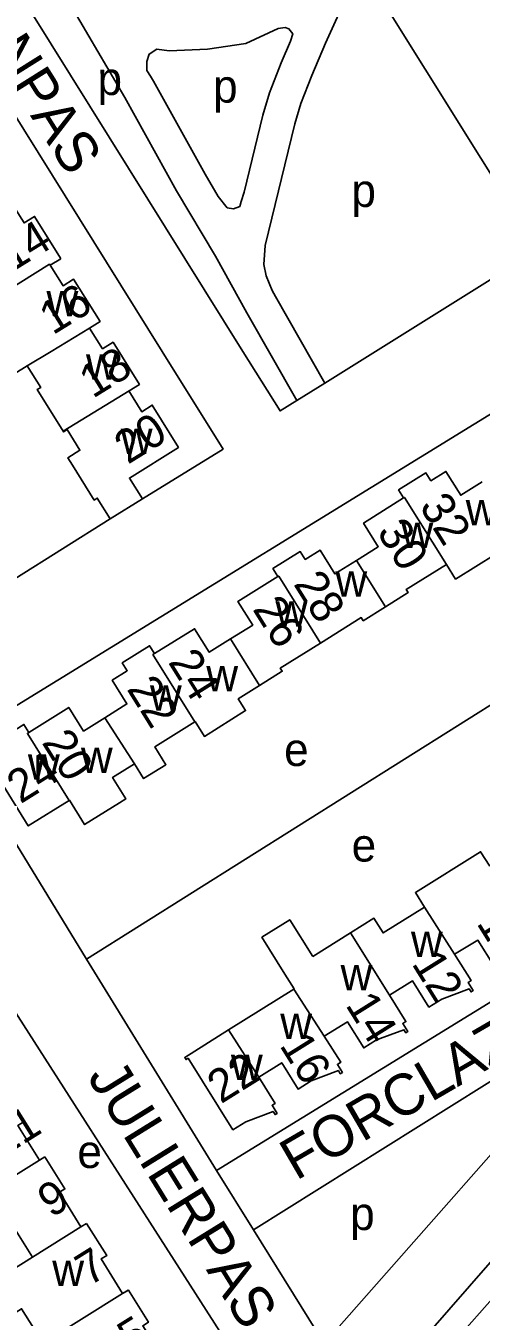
# Model space of a CAD drawing. Extents: x 158848 to 160613, y 385889 to 387762.
# Drawn here: x 159153.5 to 159208.8, y 386865.6 to 387022.2 of the extents above; entities that cross this region are included whole.
import ezdxf

# ---------------------------------------------------------------- set-up
doc = ezdxf.new("R2010")
doc.units = 0
for name, color, linetype in [('BLT_Basislijn', 7, 'Continuous'), ('BLT_Bebouwing', 7, 'Continuous'), ('BLT_Centroide', 7, 'Continuous'), ('BLT_Huisnummer', 7, 'Continuous'), ('BLT_Huisnummer_ tussenligend', 7, 'Continuous'), ('BLT_Onderverdeling_panden', 7, 'Continuous'), ('BLT_Straatnaam', 7, 'Continuous')]:
    doc.layers.add(name, color=color, linetype=linetype)

msp = doc.modelspace()

# ---------------------------------------------------------------- linework, layer by layer
at = {"layer": 'BLT_Basislijn'}
for p, q in [((159127.38, 387051.14), (159170.05, 386982.75)), ((159163.76, 386962.42), (159152.2, 386955.13)), ((159160.9, 386909.02), (159236.2, 386956.34)), ((159160.9, 386909.02), (159176.65, 386883.38)), ((159176.65, 386883.38), (159181.14, 386876.17)), ((159181.14, 386876.17), (159189.75, 386862.37))]:
    msp.add_line(p, q, dxfattribs=at)
for points in [[(159137.97, 387049.83), (159140.6, 387049.83), (159141.98, 387049.49), (159142.97, 387048.99), (159144.37, 387048.23), (159145.02, 387047.58), (159145.74, 387046.72), (159147.69, 387044.46), (159148.49, 387043.39), (159149.49, 387041.67), (159158.97, 387024.7), (159165.54, 387013.55), (159171.8, 387002.23), (159176.54, 386994.29), (159180.35, 386987.43), (159186.41, 386976.78)], [(159179.86, 386982.75), (159137.97, 387049.83)], [(159195.05, 387028.15), (159192.99, 387026.26), (159191.51, 387023.71), (159189.88, 387020.15), (159188.22, 387016.23), (159186.89, 387012.82), (159186.16, 387010.36), (159182.58, 386995.58)], [(159195.05, 387028.15), (159215.7, 386995.08), (159195.96, 386982.75)], [(159170.92, 387019.2), (159175.56, 387019.43), (159180.23, 387020.09), (159184.13, 387021.92)], [(159184.13, 387021.92), (159184.99, 387022.03), (159185.45, 387021.88), (159185.91, 387021.27), (159185.64, 387020.4)], [(159185.64, 387020.4), (159184.52, 387017.74), (159183.1, 387014.12), (159182.3, 387011.39), (159180.04, 387002.06)], [(159170.92, 387019.2), (159169.41, 387019.43), (159168.49, 387018.82), (159168.19, 387017.9), (159168.19, 387016.83), (159168.65, 387016.14)], [(159168.65, 387016.14), (159169.01, 387015.53), (159175.27, 387004.23), (159176.87, 387001.54)], [(159176.87, 387001.54), (159177.97, 387000.17), (159178.73, 387000.02), (159179.49, 387000.33), (159179.65, 387000.94), (159180.04, 387002.06)], [(159182.58, 386995.58), (159182.4, 386993.3), (159182.7, 386991.92), (159183.41, 386990.14)], [(159183.41, 386990.14), (159183.83, 386989.39), (159189.8, 386978.9)], [(159170.05, 386982.75), (159177.46, 386970.89), (159167.66, 386964.86)], [(159186.41, 386976.78), (159184.38, 386975.52), (159179.86, 386982.75)], [(159195.96, 386982.75), (159189.8, 386978.9)], [(159220.45, 386981.6), (159144.84, 386935.16), (159160.9, 386909.02)], [(159189.8, 386978.9), (159186.41, 386976.78)], [(159176.65, 386883.38), (159252.82, 386930.16), (159236.2, 386956.34)], [(159187.49, 386847.55), (159135.54, 386928.59), (159130.53, 386925.54)], [(159194.56, 386854.66), (159251.14, 386919.42), (159256.83, 386923.09), (159267.95, 386905.52), (159267.38, 386904.72)], [(159181.14, 386876.17), (159221.23, 386901.24), (159222.71, 386899.76), (159189.75, 386862.37)]]:
    msp.add_lwpolyline(points, dxfattribs=at)
at = {"layer": 'BLT_Bebouwing'}
for p, q in [((159156.48, 386993.21), (159157.76, 386993.99)), ((159157.76, 386993.99), (159157.72, 386994.05)), ((159166.03, 386977.94), (159166.05, 386977.96)), ((159167.66, 386964.86), (159163.76, 386962.42)), ((159204.59, 386956.9), (159204.57, 386956.88)), ((159174.08, 386937.83), (159174.04, 386937.8)), ((159158.78, 386928.26), (159158.82, 386928.28)), ((159188.36, 386909.32), (159192.94, 386912.19)), ((159186.04, 386905.38), (159178.12, 386900.42)), ((159186.09, 386905.42), (159186.04, 386905.38)), ((159155.16, 386884.62), (159155.84, 386885.04)), ((159155.84, 386885.04), (159155.84, 386885.03)), ((159160.21, 386876.53), (159160.89, 386876.95)), ((159160.89, 386876.95), (159160.9, 386876.93)), ((159165.27, 386868.43), (159165.95, 386868.85)), ((159165.95, 386868.85), (159165.96, 386868.83))]:
    msp.add_line(p, q, dxfattribs=at)
for points in [[(159157.72, 386994.05), (159154.57, 386999.12), (159153.3, 386998.33), (159152.26, 387000)], [(159161.26, 386985.58), (159162.53, 386986.38), (159159.31, 386991.49), (159158.04, 386990.7), (159156.48, 386993.21)], [(159145.9, 386986.79), (159150.67, 386979.15), (159153.67, 386981.01)], [(159166.05, 386977.96), (159167.3, 386978.73), (159164.1, 386983.86), (159162.83, 386983.07), (159161.26, 386985.58)], [(159153.67, 386981.01), (159155.32, 386978.38), (159154.89, 386978.11), (159158.03, 386973.07)], [(159167.66, 386964.86), (159166.09, 386967.37), (159172.04, 386971.1), (159168.86, 386976.23), (159167.59, 386975.43), (159166.03, 386977.94)], [(159158.03, 386973.07), (159158.09, 386972.98), (159158.52, 386973.25), (159160.08, 386970.75), (159158.62, 386969.84), (159159.18, 386968.95)], [(159163.76, 386962.42), (159162.19, 386964.94), (159161.83, 386964.71), (159159.18, 386968.95)], [(159208.9, 386966.93), (159206.31, 386965.3), (159204.51, 386968.18), (159202.69, 386967.04), (159202.08, 386968), (159198.76, 386965.93), (159199.36, 386964.96)], [(159199.36, 386964.96), (159194.51, 386961.92), (159196.3, 386959.05), (159193.64, 386957.39)], [(159193.64, 386957.39), (159191.03, 386955.75), (159189.23, 386958.63), (159187.43, 386957.5), (159186.83, 386958.46), (159183.52, 386956.39), (159184.12, 386955.43)], [(159210.86, 386957.84), (159210.63, 386958.2), (159205.69, 386955.12), (159204.59, 386956.9)], [(159184.12, 386955.43), (159179.27, 386952.4), (159181.06, 386949.53), (159178.37, 386947.85)], [(159204.57, 386956.88), (159199.68, 386953.85), (159199.91, 386953.48), (159197.16, 386951.75)], [(159197.16, 386951.75), (159194.47, 386950.07), (159194.23, 386950.45), (159189.29, 386947.36)], [(159178.37, 386947.85), (159175.79, 386946.24), (159174, 386949.1), (159169.14, 386946.07)], [(159169.14, 386946.07), (159168.54, 386947.03), (159165.22, 386944.95), (159165.82, 386943.99), (159164, 386942.85), (159165.79, 386939.98), (159163.11, 386938.3)], [(159189.29, 386947.36), (159184.41, 386944.3), (159184.64, 386943.93), (159181.9, 386942.2)], [(159181.9, 386942.2), (159179.31, 386940.57), (159180.19, 386939.17), (159175.2, 386936.04), (159174.08, 386937.83)], [(159163.11, 386938.3), (159160.52, 386936.68), (159158.73, 386939.55), (159153.88, 386936.52)], [(159153.88, 386936.52), (159153.28, 386937.48), (159149.95, 386935.4), (159150.55, 386934.44), (159148.75, 386933.33), (159153.81, 386925.17), (159158.78, 386928.26)], [(159174.04, 386937.8), (159169.17, 386934.75), (159170.52, 386932.6), (159167.81, 386930.91), (159166.7, 386932.7)], [(159166.7, 386932.7), (159164.04, 386931.06), (159165.65, 386928.45), (159164.9, 386927.97)], [(159158.82, 386928.28), (159160.65, 386925.33), (159164.9, 386927.97)], [(159201.91, 386915.31), (159200.8, 386917.09), (159208.73, 386922.04), (159209.83, 386920.29)], [(159192.94, 386912.19), (159195.77, 386913.97), (159196.88, 386912.18), (159201.91, 386915.31)], [(159188.36, 386909.32), (159185.55, 386913.79), (159182.17, 386911.67), (159184.97, 386907.19), (159186.09, 386905.42)], [(159205.56, 386909.61), (159208.39, 386911.31), (159210.37, 386908.14), (159211.93, 386909.12), (159215.24, 386910.36), (159215.47, 386909.98), (159215.73, 386910.14), (159215.12, 386911.12), (159215.48, 386911.34), (159213.5, 386914.51)], [(159197.67, 386904.62), (159200.46, 386906.36), (159202.45, 386903.19), (159204.02, 386904.17), (159207.33, 386905.41), (159207.56, 386905.03), (159207.82, 386905.19), (159207.21, 386906.17), (159207.57, 386906.4), (159205.56, 386909.61)], [(159189.75, 386899.67), (159192.55, 386901.42), (159194.54, 386898.24), (159196.1, 386899.21), (159199.41, 386900.44), (159199.64, 386900.08), (159199.89, 386900.23), (159199.28, 386901.21), (159199.66, 386901.44), (159197.67, 386904.62)], [(159178.12, 386900.42), (159172.8, 386897.08), (159172.96, 386896.83), (159173.22, 386896.99), (159178.66, 386888.3), (159180.23, 386889.28), (159183.53, 386890.53), (159183.77, 386890.14), (159184.02, 386890.3), (159183.41, 386891.28), (159183.78, 386891.5), (159181.79, 386894.68)], [(159181.79, 386894.68), (159184.58, 386896.43), (159186.57, 386893.25), (159188.15, 386894.24), (159191.46, 386895.48), (159191.69, 386895.1), (159191.95, 386895.26), (159191.34, 386896.23), (159191.74, 386896.49), (159189.75, 386899.67)], [(159150.78, 386893.13), (159153.21, 386889.24), (159152.53, 386888.82), (159155.16, 386884.62)], [(159155.84, 386885.03), (159158.27, 386881.14), (159157.6, 386880.72), (159160.21, 386876.53)], [(159154.33, 386872.84), (159151.7, 386877.05), (159137.97, 386868.48), (159135.53, 386872.39), (159145.51, 386878.61)], [(159160.9, 386876.93), (159163.33, 386873.05), (159162.65, 386872.63), (159165.27, 386868.43)], [(159155.61, 386862.41), (159153, 386866.6), (159145.27, 386861.78), (159142.84, 386865.67), (159154.33, 386872.84)], [(159165.96, 386868.83), (159168.39, 386864.95), (159167.71, 386864.53), (159170.33, 386860.34)], [(159212.94, 386865.35), (159210.12, 386867.81), (159206.14, 386863.26), (159208.96, 386860.8), (159206.82, 386858.35)]]:
    msp.add_lwpolyline(points, dxfattribs=at)
at = {"layer": 'BLT_Onderverdeling_panden'}
for p, q in [((159161.26, 386985.58), (159156.58, 386982.75)), ((159156.58, 386982.75), (159153.67, 386981.01)), ((159166.05, 386977.96), (159158.03, 386973.07)), ((159193.64, 386957.39), (159197.16, 386951.75)), ((159178.37, 386947.85), (159181.9, 386942.2)), ((159163.11, 386938.3), (159166.7, 386932.7)), ((159201.91, 386915.31), (159205.56, 386909.61)), ((159192.94, 386912.19), (159197.67, 386904.62)), ((159186.04, 386905.38), (159189.75, 386899.67)), ((159178.12, 386900.42), (159181.79, 386894.68)), ((159155.16, 386884.62), (159155.84, 386885.03)), ((159145.51, 386878.61), (159155.16, 386884.62)), ((159154.33, 386872.84), (159160.21, 386876.53)), ((159160.21, 386876.53), (159160.9, 386876.93)), ((159155.61, 386862.41), (159165.27, 386868.43)), ((159165.27, 386868.43), (159165.96, 386868.83))]:
    msp.add_line(p, q, dxfattribs=at)
for points in [[(159156.48, 386993.21), (159156.37, 386993.32), (159145.9, 386986.79)], [(159199.36, 386964.96), (159199.48, 386965.03), (159204.57, 386956.88)], [(159184.12, 386955.43), (159184.22, 386955.49), (159189.29, 386947.36)], [(159169.14, 386946.07), (159168.95, 386945.95), (159174.04, 386937.8)], [(159153.88, 386936.52), (159153.7, 386936.4), (159158.78, 386928.26)]]:
    msp.add_lwpolyline(points, dxfattribs=at)

# ---------------------------------------------------------------- texts
at = {"layer": 'BLT_Centroide'}
for s, p in [('p', (159162.22, 387013.85)), ('p', (159176.25, 387012.93)), ('p', (159193.04, 387000.27)), ('w', (159156.02, 386987)), ('w', (159160.82, 386979.31)), ('w', (159165.03, 386970.28)), ('w', (159206.91, 386961.66)), ('w', (159199.11, 386958.88)), ('w', (159191.09, 386953)), ('w', (159183.83, 386949.33)), ('w', (159175.42, 386941.5)), ('w', (159168.58, 386939.17)), ('e', (159184.87, 386932.44)), ('w', (159153.77, 386930.77)), ('w', (159160.2, 386931.61)), ('e', (159193.07, 386920.85)), ('w', (159200.27, 386909.28)), ('w', (159191.72, 386905.22)), ('w', (159184.4, 386899.31)), ('w', (159178.41, 386894.34)), ('e', (159159.77, 386883.67)), ('p', (159192.89, 386876.14)), ('w', (159156.72, 386869.34))]:
    msp.add_text(s, height=4, dxfattribs=at).set_placement(p)
at = {"layer": 'BLT_Huisnummer'}
for s, rotation, p in [('14', 31.7024, (159151.83, 386992.32)), ('20', 31.7024, (159165.9, 386968.98)), ('28', 301.9589, (159185.94, 386954.53)), ('24', 301.9589, (159170.72, 386945.05)), ('20', 301.9589, (159155.38, 386935.3)), ('24', 31.9847, (159152.87, 386927.79)), ('10', 301.9893, (159208.16, 386913.38)), ('16', 301.9893, (159184.24, 386898.55)), ('22', 31.9939, (159177.2, 386891.39)), ('9', 31.9846, (159156.61, 386877.55)), ('5', 31.9846, (159166.29, 386860.99))]:
    msp.add_text(s, height=4, rotation=rotation, dxfattribs=at).set_placement(p)
at = {"layer": 'BLT_Huisnummer_ tussenligend'}
for s, rotation, p in [('16', 31.7024, (159156.79, 386984.67)), ('18', 31.7024, (159161.64, 386976.97)), ('32', 301.9589, (159201.21, 386963.95)), ('30', 301.9589, (159196.05, 386960.84)), ('26', 301.9589, (159180.97, 386951.48)), ('22', 301.9589, (159165.7, 386941.79)), ('12', 301.9893, (159200.28, 386908.47)), ('14', 301.9893, (159192.25, 386903.45)), ('11', 31.9846, (159150.63, 386884.9)), ('7', 31.9846, (159161.19, 386869.26))]:
    msp.add_text(s, height=4, rotation=rotation, dxfattribs=at).set_placement(p)
at = {"layer": 'BLT_Straatnaam'}
for s, rotation, p in [('SIMPLONPAS', 302.0777, (159135.65, 387040.65)), ('FORCLAZPAS', 30.174, (159186.33, 386882.08)), ('JULIERPAS', 301.7229, (159160.89, 386894.72))]:
    msp.add_text(s, height=5, rotation=rotation, dxfattribs=at).set_placement(p)

doc.saveas('drawing.dxf')
